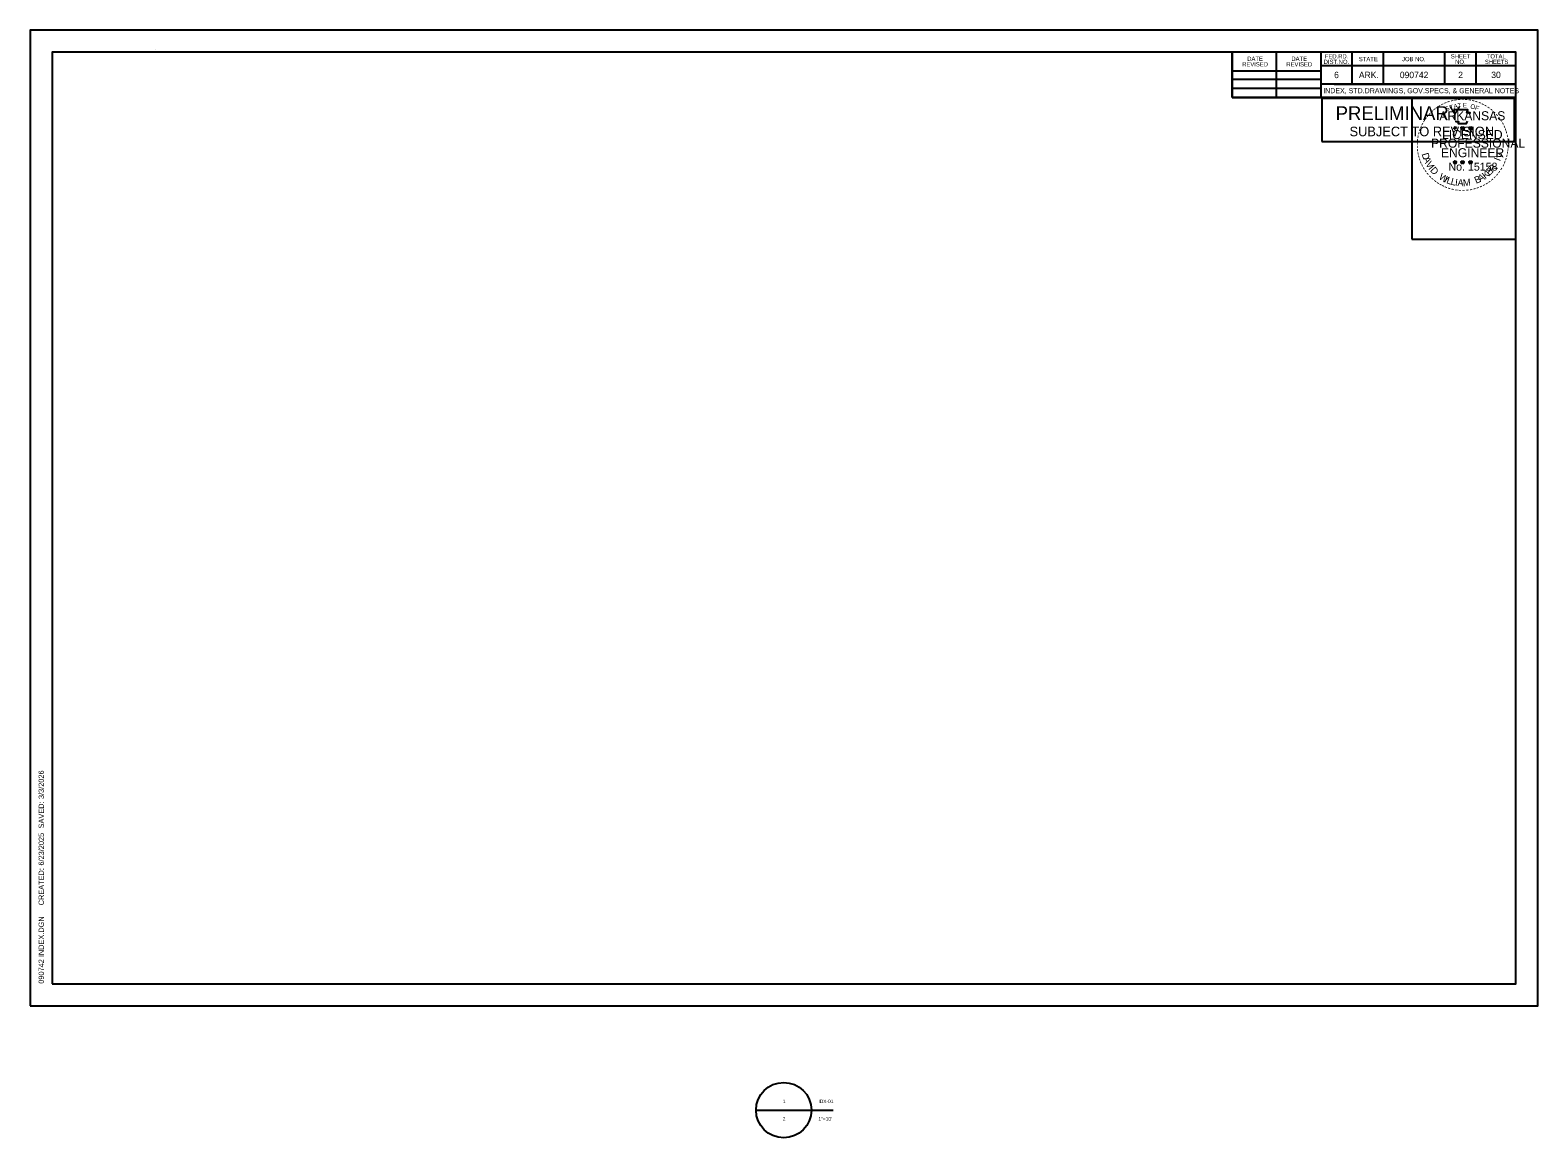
# Model space of a CAD drawing. Extents: x 0 to 464, y -15 to 110.
import ezdxf

# ---------------------------------------------------------------- set-up
doc = ezdxf.new("R2010")
doc.units = 0
for name, color, linetype in [('Default', 7, 'Continuous'), ('SHET_Annotations', 7, 'Continuous'), ('SHET_Border-Lines', 7, 'Continuous'), ('SHET_Border-Text', 7, 'Continuous'), ('SHET_Stamp-Prelim', 7, 'Continuous'), ('SHET_Stamp-Seal', 7, 'Continuous')]:
    doc.layers.add(name, color=color, linetype=linetype)

msp = doc.modelspace()

# ---------------------------------------------------------------- linework, layer by layer
at = {"layer": 'Default'}
for p, q in [((81.85, -11.75), (88.1, -11.75)), ((85, -11.75), (90.53, -11.75))]:
    msp.add_line(p, q, dxfattribs=at)
msp.add_circle((84.97, -11.75), 3.12, dxfattribs=at)
at = {"layer": 'SHET_Border-Lines'}
for p, q in [((14.11, 107.86), (14.11, 107.86)), ((14.11, 107.86), (14.11, 107.86)), ((135.55, 102.41), (135.55, 107.5)), ((140.54, 102.41), (140.54, 107.5)), ((145.52, 107.5), (145.52, 102.41)), ((149.01, 107.5), (149.01, 103.92)), ((152.55, 107.5), (152.55, 103.92)), ((159.47, 107.5), (159.47, 103.92)), ((163.01, 107.5), (163.01, 103.92)), ((135.55, 105.43), (145.52, 105.43)), ((167.5, 105.98), (145.52, 105.98)), ((167.5, 105.99), (167.5, 105.99)), ((135.55, 104.47), (145.52, 104.47)), ((167.5, 103.92), (145.52, 103.92)), ((147.03, 103.92), (167.5, 103.92)), ((135.55, 103.47), (145.52, 103.47)), ((167.5, 102.41), (135.55, 102.41))]:
    msp.add_line(p, q, dxfattribs=at)
for points in [[(0, 0), (170, 0), (170, 110), (0, 110)], [(2.5, 2.5), (167.5, 2.5), (167.5, 107.5), (2.5, 107.5)], [(135.55, 102.41), (167.5, 102.41), (167.5, 107.5), (135.55, 107.5)]]:
    msp.add_lwpolyline(points, close=True, dxfattribs=at)
at = {"layer": 'SHET_Stamp-Prelim'}
msp.add_lwpolyline([(145.64, 97.43), (167.38, 97.43), (167.38, 102.29), (145.64, 102.29)], close=True, dxfattribs=at)
at = {"layer": 'SHET_Stamp-Seal'}
for p, q in [((160.48, 99.03), (160.66, 98.97)), ((160.48, 99.03), (160.61, 99)), ((160.48, 99.03), (160.6, 98.96)), ((160.55, 98.82), (160.66, 98.97)), ((160.55, 98.82), (160.61, 98.94)), ((160.55, 98.82), (160.66, 98.93)), ((160.66, 99.15), (160.64, 99.03)), ((160.66, 98.97), (160.66, 99.15)), ((160.66, 99.15), (160.68, 99.03)), ((160.83, 99.03), (160.66, 98.97)), ((160.77, 98.82), (160.66, 98.97)), ((160.77, 98.82), (160.66, 98.93)), ((160.83, 99.03), (160.69, 99)), ((160.77, 98.82), (160.7, 98.97)), ((160.83, 99.03), (160.73, 98.97)), ((161.33, 99.03), (161.51, 98.97)), ((161.33, 99.03), (161.46, 99)), ((161.33, 99.03), (161.45, 98.96)), ((161.4, 98.82), (161.51, 98.97)), ((161.4, 98.82), (161.46, 98.94)), ((161.4, 98.82), (161.51, 98.93)), ((161.51, 99.15), (161.49, 99.03)), ((161.51, 98.97), (161.51, 99.15)), ((161.51, 99.15), (161.53, 99.03)), ((161.69, 99.03), (161.51, 98.97)), ((161.62, 98.82), (161.51, 98.97)), ((161.62, 98.82), (161.51, 98.93)), ((161.69, 99.03), (161.54, 99)), ((161.62, 98.82), (161.55, 98.97)), ((161.69, 99.03), (161.58, 98.97)), ((162.23, 99.02), (162.41, 98.96)), ((162.23, 99.02), (162.36, 99)), ((162.23, 99.02), (162.35, 98.96)), ((162.3, 98.81), (162.41, 98.96)), ((162.3, 98.81), (162.36, 98.94)), ((162.3, 98.81), (162.41, 98.92)), ((162.41, 99.15), (162.39, 99.02)), ((162.41, 98.96), (162.41, 99.15)), ((162.41, 99.15), (162.43, 99.02)), ((162.59, 99.02), (162.41, 98.96)), ((162.52, 98.81), (162.41, 98.96)), ((162.52, 98.81), (162.41, 98.92)), ((162.59, 99.02), (162.44, 98.99)), ((162.52, 98.81), (162.45, 98.96)), ((162.59, 99.02), (162.48, 98.97)), ((160.66, 95.29), (160.63, 95.16)), ((160.66, 95.11), (160.66, 95.29)), ((160.66, 95.29), (160.68, 95.16)), ((161.51, 95.29), (161.49, 95.16)), ((161.51, 95.11), (161.51, 95.29)), ((161.51, 95.29), (161.53, 95.16)), ((162.41, 95.29), (162.39, 95.16)), ((162.41, 95.1), (162.41, 95.29)), ((162.41, 95.29), (162.43, 95.16)), ((160.48, 95.16), (160.66, 95.11)), ((160.48, 95.16), (160.61, 95.14)), ((160.48, 95.16), (160.6, 95.1)), ((160.55, 94.95), (160.66, 95.11)), ((160.55, 94.95), (160.61, 95.08)), ((160.55, 94.95), (160.65, 95.07)), ((160.76, 94.95), (160.65, 95.06)), ((160.83, 95.16), (160.66, 95.11)), ((160.76, 94.95), (160.66, 95.11)), ((160.83, 95.16), (160.69, 95.14)), ((160.76, 94.95), (160.69, 95.1)), ((160.83, 95.16), (160.73, 95.11)), ((161.33, 95.16), (161.51, 95.11)), ((161.33, 95.16), (161.46, 95.14)), ((161.33, 95.16), (161.45, 95.1)), ((161.4, 94.95), (161.51, 95.11)), ((161.4, 94.95), (161.46, 95.08)), ((161.4, 94.95), (161.51, 95.07)), ((161.68, 95.16), (161.51, 95.11)), ((161.62, 94.95), (161.51, 95.11)), ((161.62, 94.95), (161.51, 95.06)), ((161.68, 95.16), (161.54, 95.14)), ((161.62, 94.95), (161.55, 95.1)), ((161.68, 95.16), (161.58, 95.11)), ((162.23, 95.16), (162.41, 95.1)), ((162.23, 95.16), (162.36, 95.13)), ((162.23, 95.16), (162.35, 95.1)), ((162.3, 94.95), (162.41, 95.1)), ((162.3, 94.95), (162.36, 95.07)), ((162.3, 94.95), (162.41, 95.06)), ((162.58, 95.16), (162.41, 95.1)), ((162.52, 94.95), (162.41, 95.1)), ((162.52, 94.95), (162.41, 95.06)), ((162.58, 95.16), (162.44, 95.13)), ((162.52, 94.95), (162.45, 95.1)), ((162.58, 95.16), (162.48, 95.11))]:
    msp.add_line(p, q, dxfattribs=at)
msp.add_lwpolyline([(155.8, 86.43), (167.5, 86.43), (167.5, 102.41), (155.8, 102.41)], close=True, dxfattribs=at)
for points in [[(160.5, 101), (160.64, 100.58)], [(162.29, 100.53), (162.36, 100.68), (162.01, 100.67), (162.09, 101), (160.5, 101)], [(160.75, 99.77), (160.75, 99.72), (161.04, 99.71), (161.01, 99.47), (161.96, 99.47), (162.07, 99.75)], [(161.51, 99.15), (161.62, 98.82), (161.33, 99.03), (161.69, 99.03), (161.4, 98.82), (161.51, 99.15)], [(162.41, 99.15), (162.52, 98.81), (162.23, 99.02), (162.59, 99.02), (162.3, 98.81), (162.41, 99.15)], [(160.66, 95.29), (160.76, 94.95), (160.48, 95.16), (160.83, 95.16), (160.55, 94.95), (160.66, 95.29)], [(161.51, 95.29), (161.62, 94.95), (161.33, 95.16), (161.68, 95.16), (161.4, 94.95), (161.51, 95.29)], [(162.41, 95.29), (162.52, 94.95), (162.23, 95.16), (162.58, 95.16), (162.3, 94.95), (162.41, 95.29)]]:
    msp.add_lwpolyline(points, dxfattribs=at)
for centre, radius in [((160.66, 98.97), 0.0878), ((160.66, 98.97), 0.0737), ((160.66, 98.97), 0.059), ((160.66, 98.97), 0.0505), ((160.66, 98.97), 0.0381), ((160.66, 98.97), 0.0253), ((160.66, 98.97), 0.0151), ((161.51, 98.97), 0.0878), ((161.51, 98.97), 0.0737), ((161.51, 98.97), 0.059), ((161.51, 98.97), 0.0505), ((161.51, 98.97), 0.0381), ((161.51, 98.97), 0.0253), ((161.51, 98.97), 0.0151), ((162.41, 98.96), 0.0878), ((162.41, 98.96), 0.0737), ((162.41, 98.96), 0.059), ((162.41, 98.96), 0.0505), ((162.41, 98.96), 0.0381), ((162.41, 98.96), 0.0253), ((162.41, 98.96), 0.0151), ((160.65, 95.11), 0.0878), ((160.65, 95.11), 0.0737), ((160.65, 95.11), 0.059), ((160.65, 95.11), 0.0505), ((160.65, 95.11), 0.0381), ((160.65, 95.11), 0.0253), ((160.65, 95.11), 0.0151), ((161.51, 95.11), 0.0878), ((161.51, 95.11), 0.0737), ((161.51, 95.11), 0.059), ((161.51, 95.11), 0.0505), ((161.51, 95.11), 0.0381), ((161.51, 95.11), 0.0253), ((161.51, 95.11), 0.0151), ((162.41, 95.1), 0.0878), ((162.41, 95.1), 0.0737), ((162.41, 95.1), 0.059), ((162.41, 95.1), 0.0505), ((162.41, 95.1), 0.0381), ((162.41, 95.1), 0.0253), ((162.41, 95.1), 0.0151)]:
    msp.add_circle(centre, radius, dxfattribs=at)

# ---------------------------------------------------------------- texts
at = {"layer": 'Default'}
for s, p in [('1', (84.87, -10.96)), ('IDX-01', (88.88, -10.96)), ('2', (84.86, -12.93)), ('1"=10\'', (88.88, -12.93))]:
    msp.add_text(s, height=0.394, dxfattribs=at).set_placement(p)
at = {"layer": 'SHET_Annotations'}
for s, p in [('6', (147.03, 104.59)), ('ARK.', (149.82, 104.59)), ('090742', (154.44, 104.59)), ('2', (161.02, 104.59)), ('30', (164.75, 104.6))]:
    msp.add_text(s, height=0.72, dxfattribs=at).set_placement(p)
at = {"layer": 'SHET_Border-Text'}
for s, height, p in [('FED.RD.', 0.48, (145.98, 106.81)), ('SHEET', 0.48, (160.19, 106.81)), ('TOTAL', 0.48, (164.24, 106.81)), ('REVISED', 0.48, (136.66, 105.91)), ('DATE', 0.48, (137.23, 106.54)), ('REVISED', 0.48, (141.64, 105.91)), ('DATE', 0.48, (142.21, 106.54)), ('DIST.NO.', 0.48, (145.85, 106.19)), ('STATE', 0.48, (149.82, 106.5)), ('JOB NO.', 0.48, (154.69, 106.5)), ('NO.', 0.48, (160.68, 106.19)), ('SHEETS', 0.48, (164.02, 106.19)), ('INDEX, STD.DRAWINGS, GOV.SPECS, & GENERAL NOTES', 0.5743, (145.8, 102.89))]:
    msp.add_text(s, height=height, dxfattribs=at).set_placement(p)
for s, p in [('3/3/2026', (1.55, 23.32)), ('  SAVED: ', (1.55, 19.55)), ('6/23/2025', (1.55, 15.82)), ('     CREATED: ', (1.55, 10.19)), ('090742 INDEX.DGN', (1.55, 2.5))]:
    msp.add_text(s, height=0.6, rotation=90, dxfattribs=at).set_placement(p)
at = {"layer": 'SHET_Stamp-Prelim'}
for s, height, p in [('PRELIMINARY', 1.56, (147.2, 99.86)), ('SUBJECT TO REVISION', 1.08, (148.77, 98.04))]:
    msp.add_text(s, height=height, dxfattribs=at).set_placement(p)
at = {"layer": 'SHET_Stamp-Seal'}
for s, height, rotation, p in [('-', 0.816, 19.1761, (159.86, 101.58)), ('-', 0.816, 13.6302, (160.24, 101.7)), ('-', 0.816, 10.2193, (160.59, 101.78)), ('-', 0.816, 5.8968, (160.96, 101.84)), ('-', 0.816, 0.1862, (161.36, 101.88)), ('-', 0.816, 357.743, (161.72, 101.87)), ('-', 0.816, 352.1617, (162.1, 101.84)), ('-', 0.816, 347.2049, (162.47, 101.78)), ('-', 0.816, 342.3362, (162.79, 101.7)), ('-', 0.816, 50.6142, (157.72, 99.99)), ('-', 0.816, 48.4231, (157.92, 100.24)), ('-', 0.816, 42.9622, (158.15, 100.48)), ('-', 0.816, 38.9507, (158.37, 100.7)), ('-', 0.816, 36.2317, (158.62, 100.89)), ('-', 0.816, 34.0636, (158.91, 101.09)), ('-', 0.816, 28.7918, (159.22, 101.28)), ('-', 0.816, 24.3072, (159.54, 101.44)), ('S', 0.51, 21.594, (159.66, 100.84)), ('T', 0.51, 16.4036, (160.13, 101.01)), ('A', 0.51, 11.2132, (160.55, 101.14)), ('T', 0.51, 6.0228, (160.98, 101.22)), ('E', 0.51, 0.8323, (161.55, 101.28)), ('O', 0.51, 350.4515, (162.36, 101.17)), ('F', 0.51, 340.0707, (162.85, 101.05)), ('-', 0.816, 337.8551, (163.17, 101.59)), ('-', 0.816, 334.1211, (163.49, 101.45)), ('-', 0.816, 329.6409, (163.79, 101.31)), ('-', 0.816, 325.8627, (164.11, 101.12)), ('-', 0.816, 320.5297, (164.43, 100.91)), ('-', 0.816, 315.5786, (164.73, 100.66)), ('-', 0.816, 309.8797, (165.02, 100.38)), ('-', 0.816, 72.3945, (156.94, 98.49)), ('-', 0.816, 67.7743, (157.05, 98.81)), ('-', 0.816, 62.8713, (157.18, 99.12)), ('-', 0.816, 58.0706, (157.34, 99.43)), ('-', 0.816, 54.2325, (157.51, 99.7)), ('-', 0.816, 306.6522, (165.29, 100.07)), ('-', 0.714, 303.6753, (165.54, 99.78)), ('-', 0.816, 299.6684, (165.7, 99.47)), ('-', 0.816, 294.6628, (165.86, 99.16)), ('-', 0.816, 290.5728, (166, 98.86)), ('-', 0.816, 285.1233, (166.11, 98.57)), ('-', 0.816, 94.1959, (156.74, 96.68)), ('-', 0.816, 89.0622, (156.72, 97.05)), ('-', 0.816, 85.1863, (156.73, 97.41)), ('-', 0.816, 81.2013, (156.77, 97.76)), ('-', 0.816, 75.461, (156.84, 98.12)), ('-', 0.816, 280.5493, (166.22, 98.19)), ('-', 0.816, 276.5962, (166.3, 97.8)), ('-', 0.816, 274.3301, (166.33, 97.43)), ('-', 0.816, 269.9407, (166.35, 97.11)), ('-', 0.816, 98.9479, (156.77, 96.34)), ('-', 0.816, 101.7149, (156.84, 95.97)), ('-', 0.816, 105.4578, (156.93, 95.66)), ('-', 0.816, 109.0874, (157.04, 95.34)), ('-', 0.816, 114.0643, (157.16, 95.04)), ('D', 0.785, 286.2848, (156.89, 96.04)), ('A', 0.785, 292.7835, (157.04, 95.53)), ('V', 0.785, 300.7936, (157.3, 94.92)), ('I', 0.785, 69.0301, (165.75, 95.17)), ('V', 0.785, 72.6573, (165.86, 95.44)), ('-', 0.816, 247.8887, (166.04, 95.38)), ('-', 0.816, 252.8681, (166.15, 95.72)), ('-', 0.816, 255.7626, (166.25, 96.09)), ('-', 0.816, 260.9953, (166.3, 96.43)), ('-', 0.816, 263.5172, (166.34, 96.77)), ('-', 0.816, 115.7289, (157.32, 94.72)), ('-', 0.816, 120.4471, (157.5, 94.42)), ('-', 0.816, 125.8934, (157.71, 94.14)), ('-', 0.816, 130.7181, (157.94, 93.86)), ('I', 0.785, 308.3502, (157.62, 94.4)), ('-', 0.816, 134.2238, (158.21, 93.58)), ('D', 0.785, 311.9774, (157.8, 94.16)), ('W', 0.785, 328.0731, (158.76, 93.26)), ('I', 0.785, 336.6877, (159.36, 92.9)), ('B', 0.785, 22.8589, (163.04, 92.67)), ('A', 0.785, 28.9042, (163.5, 92.86)), ('K', 0.785, 36.9143, (164.07, 93.19)), ('E', 0.785, 44.0175, (164.53, 93.54)), ('R', 0.785, 50.3651, (164.91, 93.9)), ('-', 0.816, 225.7653, (165.04, 93.76)), (',', 0.785, 57.4684, (165.27, 94.35)), ('-', 0.816, 231.2538, (165.28, 94.05)), ('-', 0.816, 233.8452, (165.5, 94.34)), ('-', 0.816, 239.0712, (165.7, 94.67)), ('-', 0.816, 244.6197, (165.91, 95.06)), ('-', 0.816, 138.9338, (158.48, 93.34)), ('-', 0.816, 144.6463, (158.76, 93.13)), ('-', 0.816, 148.0898, (159.04, 92.94)), ('-', 0.816, 151.5704, (159.34, 92.78)), ('-', 0.816, 154.6002, (159.61, 92.65)), ('-', 0.816, 158.5612, (159.92, 92.52)), ('L', 0.785, 340.3149, (159.63, 92.77)), ('-', 0.816, 162.7983, (160.27, 92.41)), ('L', 0.785, 346.6625, (160.12, 92.6)), ('-', 0.816, 167.5555, (160.64, 92.33)), ('-', 0.816, 173.1155, (161.03, 92.27)), ('I', 0.785, 353.0101, (160.63, 92.47)), ('A', 0.785, 356.6373, (160.92, 92.43)), ('-', 0.816, 176.5183, (161.41, 92.25)), ('-', 0.816, 181.5918, (161.79, 92.26)), ('M', 0.785, 4.6473, (161.58, 92.4)), ('-', 0.816, 185.8167, (162.21, 92.3)), ('-', 0.816, 191.2858, (162.58, 92.36)), ('-', 0.816, 195.4743, (162.95, 92.47)), ('-', 0.816, 199.4643, (163.29, 92.59)), ('-', 0.816, 204.2516, (163.61, 92.73)), ('-', 0.816, 207.3568, (163.93, 92.89)), ('-', 0.816, 212.2491, (164.22, 93.07)), ('-', 0.816, 215.7363, (164.49, 93.26)), ('-', 0.816, 221.0851, (164.77, 93.5))]:
    msp.add_text(s, height=height, rotation=rotation, dxfattribs=at).set_placement(p)
for s, height, p in [('ARKANSAS', 1.02, (158.9, 99.84)), ('LICENSED', 1.02, (159.2, 97.72)), ('PROFESSIONAL', 1.02, (157.96, 96.75)), ('ENGINEER', 1.02, (159.08, 95.67)), ('No. 15158', 0.896, (159.92, 94.16)), ('AAMU', 0.0000102, (161.47, 92.4))]:
    msp.add_text(s, height=height, dxfattribs=at).set_placement(p)

doc.saveas('drawing.dxf')
